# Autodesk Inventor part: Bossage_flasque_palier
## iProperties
Shininess: 64.0
Length Units: 11269
Angle Units: 11279
Time Units: 11290
Mass Units: 11283
Length Display Precision: 3
Angle Display Precision: 2
Compacted: True
Part Number: Bossage_flasque_palier
Document SubType Name: Modeling
Created: 2008-02
Material: Acier inoxydable, austénitique
Designer: Pascal
Density: 0.0
Volumn: 0.0
Area: 0.0
PropertySet Name: Model Information
Control State: 0
Master: False
Checked Out: False
DESIGNATION: pièce
Author: Pascal
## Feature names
1. Extrusion1
2. Extrusion2
3. Chanfrein1 [Chamfer]
4. Extrusion3
5. Chanfrein2 [Chamfer]
